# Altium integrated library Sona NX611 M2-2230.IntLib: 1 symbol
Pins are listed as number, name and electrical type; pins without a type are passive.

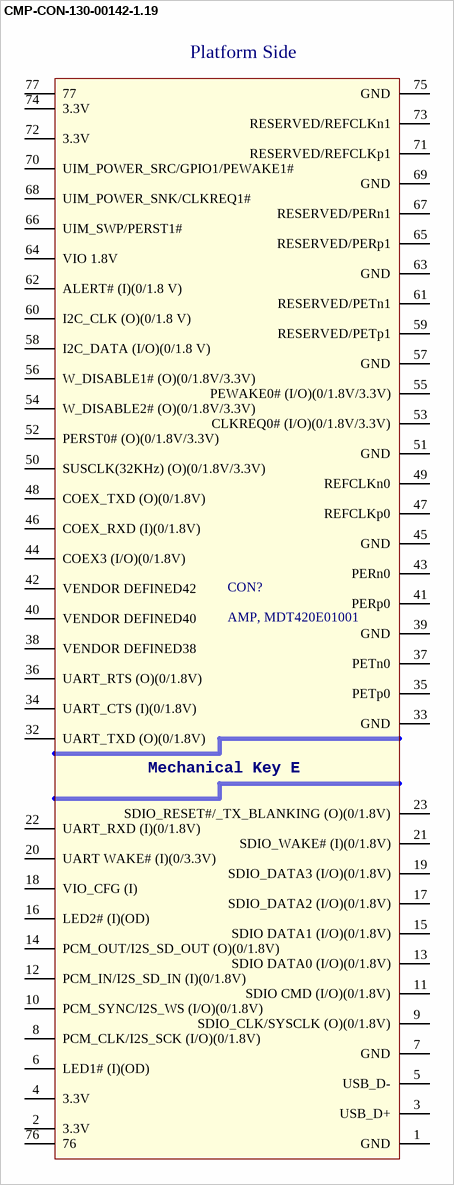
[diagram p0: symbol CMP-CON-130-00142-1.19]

## CMP-CON-130-00142-1.19
designator CON?, comment AMP, MDT420E01001
CON, SMT, M.2 Key-E, 74pins, 0.5mm, Height 2.4mm; Rows: 2; Substitutes Allowed: NO
footprint AMP, MDT420E01001, Mounting holes (AMP, MDT420E01001, M2, Key-E, w/Mounting holes)
footprint AMP, MDT420E01001 (AMP, MDT420E01001, M2, Key-E,)
pins: 1 GND (power), 2 3.3V (power), 3 USB_D+, 4 3.3V (power), 5 USB_D-, 6 LED1# (I)(OD), 7 GND (power), 8 PCM_CLK/I2S_SCK (I/O)(0/1.8V), 9 SDIO_CLK/SYSCLK (O)(0/1.8V), 10 PCM_SYNC/I2S_WS (I/O)(0/1.8V), 11 SDIO CMD (I/O)(0/1.8V), 12 PCM_IN/I2S_SD_IN (I)(0/1.8V), 13 SDIO DATA0 (I/O)(0/1.8V), 14 PCM_OUT/I2S_SD_OUT (O)(0/1.8V), 15 SDIO DATA1 (I/O)(0/1.8V), 16 LED2# (I)(OD), 17 SDIO_DATA2 (I/O)(0/1.8V), 18 VIO_CFG (I) (power), 19 SDIO_DATA3 (I/O)(0/1.8V), 20 UART WAKE# (I)(0/3.3V), 21 SDIO_WAKE# (I)(0/1.8V), 22 UART_RXD (I)(0/1.8V), 23 SDIO_RESET#/_TX_BLANKING (O)(0/1.8V), 32 UART_TXD (O)(0/1.8V), 33 GND (power), 34 UART_CTS (I)(0/1.8V), 35 PETp0, 36 UART_RTS (O)(0/1.8V), 37 PETn0, 38 VENDOR DEFINED38, 39 GND (power), 40 VENDOR DEFINED40, 41 PERp0, 42 VENDOR DEFINED42, 43 PERn0, 44 COEX3 (I/O)(0/1.8V), 45 GND (power), 46 COEX_RXD (I)(0/1.8V), 47 REFCLKp0, 48 COEX_TXD (O)(0/1.8V), 49 REFCLKn0, 50 SUSCLK(32KHz) (O)(0/1.8V/3.3V), 51 GND (power), 52 PERST0# (O)(0/1.8V/3.3V), 53 CLKREQ0# (I/O)(0/1.8V/3.3V), 54 W_DISABLE2# (O)(0/1.8V/3.3V), 55 PEWAKE0# (I/O)(0/1.8V/3.3V), 56 W_DISABLE1# (O)(0/1.8V/3.3V), 57 GND (power), 58 I2C_DATA (I/O)(0/1.8 V), 59 RESERVED/PETp1, 60 I2C_CLK (O)(0/1.8 V), 61 RESERVED/PETn1, 62 ALERT# (I)(0/1.8 V), 63 GND (power), 64 VIO 1.8V, 65 RESERVED/PERp1, 66 UIM_SWP/PERST1#, 67 RESERVED/PERn1, 68 UIM_POWER_SNK/CLKREQ1#, 69 GND (power), 70 UIM_POWER_SRC/GPIO1/PEWAKE1#, 71 RESERVED/REFCLKp1, 72 3.3V (power), 73 RESERVED/REFCLKn1, 74 3.3V (power), 75 GND (power), 76, 77
1 alternate drawing of the same symbol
